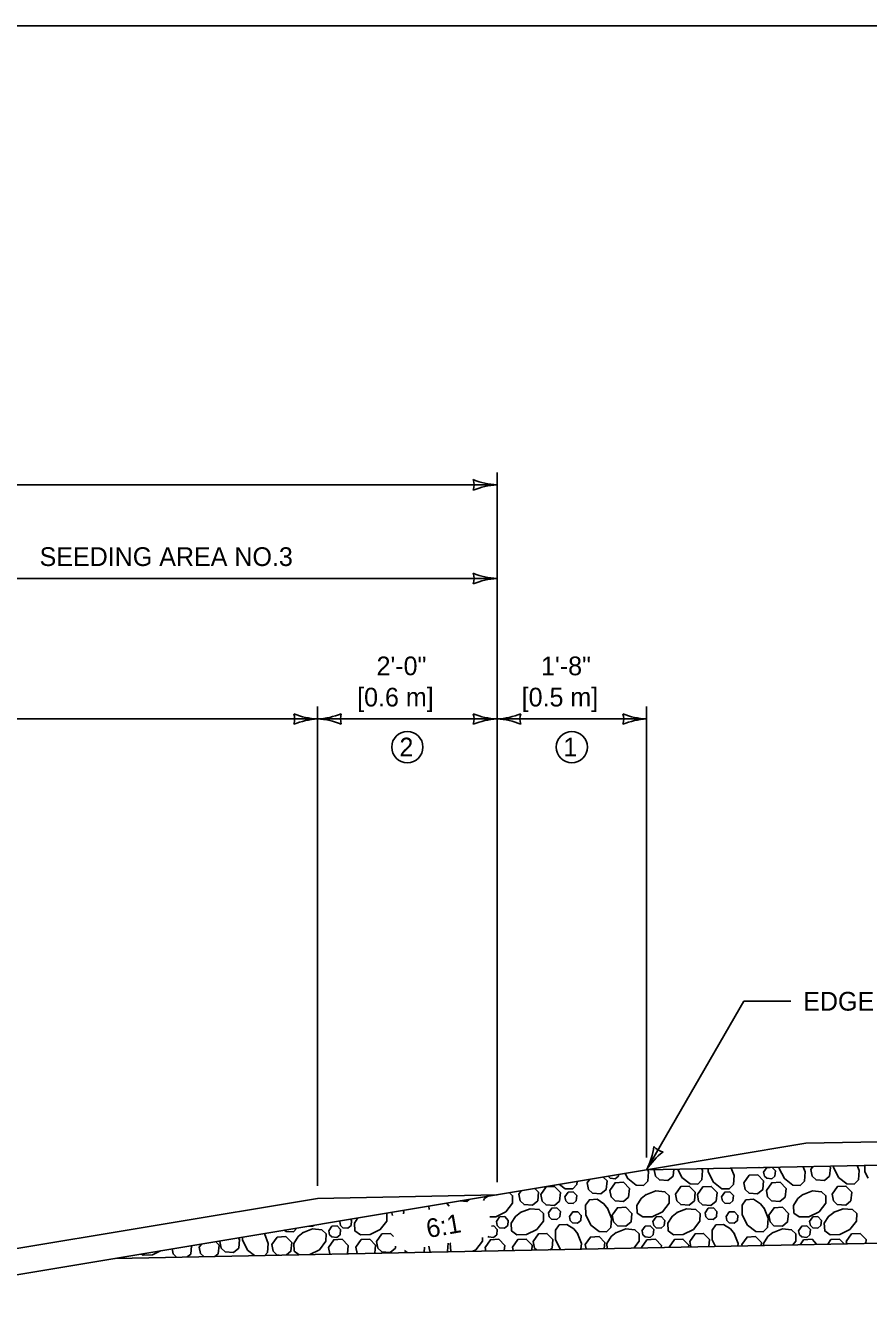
# Model space of a CAD drawing. Extents: x 49991.4 to 50021, y 49987.6 to 50011.4.
# Drawn here: x 50015.142 to 50017.842, y 50004.05 to 50008.165 of the extents above; entities that cross this region are included whole.
import ezdxf

# ---------------------------------------------------------------- set-up
doc = ezdxf.new("R2010")
doc.units = 0
for name, color, linetype in [('Level 1', 7, 'Continuous'), ('Level 2', 7, 'Continuous'), ('Level 3', 7, 'Continuous')]:
    doc.layers.add(name, color=color, linetype=linetype)

msp = doc.modelspace()

# ---------------------------------------------------------------- linework, layer by layer
at = {"layer": 'Level 1'}
for p, q in [((50020.1431, 50004.6348), (50017.6426, 50004.5848)), ((50017.6426, 50004.5848), (50017.132, 50004.4997)), ((50017.132, 50004.4997), (50020.1446, 50004.5599)), ((50014.9506, 50004.1361), (50017.132, 50004.4997)), ((50016.6527, 50004.4198), (50016.0776, 50004.4083)), ((50014.9506, 50004.2205), (50016.0776, 50004.4083)), ((50020.1496, 50004.3104), (50015.4298, 50004.216))]:
    msp.add_line(p, q, dxfattribs=at)
msp.add_lwpolyline([(50020.9378, 50008.1646), (50009.7374, 50008.1646), (50009.7374, 49999.8856), (50020.9378, 49999.8856)], close=True, dxfattribs=at)
for points in [[(50017.1357, 50004.4998), (50017.1384, 50004.4931), (50017.1358, 50004.4638), (50017.1226, 50004.4499), (50017.0988, 50004.4504), (50017.0718, 50004.4715), (50017.0634, 50004.4883)], [(50017.219, 50004.5014), (50017.2168, 50004.4796), (50017.2, 50004.4656), (50017.1731, 50004.4676), (50017.1605, 50004.4798), (50017.1565, 50004.5002)], [(50017.3093, 50004.5032), (50017.3116, 50004.4973), (50017.3091, 50004.468), (50017.2959, 50004.454), (50017.2721, 50004.4545), (50017.2451, 50004.4756), (50017.232, 50004.5017)], [(50017.4034, 50004.5051), (50017.4127, 50004.4818), (50017.4102, 50004.4525), (50017.3969, 50004.4386), (50017.3732, 50004.439), (50017.3461, 50004.4601), (50017.3298, 50004.4928), (50017.3296, 50004.5036)], [(50017.4922, 50004.5069), (50017.4922, 50004.5069), (50017.4918, 50004.5069)], [(50017.5339, 50004.5077), (50017.545, 50004.4962), (50017.5434, 50004.4797), (50017.5333, 50004.4713), (50017.5172, 50004.4725), (50017.5096, 50004.4798), (50017.5071, 50004.4925)], [(50017.5071, 50004.4925), (50017.5173, 50004.507), (50017.5277, 50004.5076)], [(50017.6336, 50004.5097), (50017.6401, 50004.4931), (50017.6376, 50004.4638), (50017.6244, 50004.4499), (50017.6006, 50004.4504), (50017.5736, 50004.4715), (50017.5573, 50004.5041), (50017.5572, 50004.5082)], [(50017.7172, 50004.5114), (50017.7213, 50004.5071), (50017.7186, 50004.4796), (50017.7018, 50004.4656), (50017.6749, 50004.4676), (50017.6622, 50004.4798), (50017.6581, 50004.5009)], [(50017.6581, 50004.5009), (50017.6648, 50004.5103)], [(50017.8071, 50004.5132), (50017.8134, 50004.4973), (50017.8109, 50004.468), (50017.7976, 50004.454), (50017.7739, 50004.4545), (50017.7469, 50004.4756), (50017.7305, 50004.5083), (50017.7305, 50004.5117)], [(50017.8416, 50004.4729), (50017.8316, 50004.4928), (50017.8312, 50004.5137)], [(50016.9093, 50004.4626), (50016.9084, 50004.4525), (50016.8952, 50004.4386), (50016.8714, 50004.439), (50016.8532, 50004.4532)], [(50016.9932, 50004.4766), (50017.0052, 50004.4641), (50017.0024, 50004.4366), (50016.9856, 50004.4226), (50016.9587, 50004.4246), (50016.9461, 50004.4369), (50016.942, 50004.4579)], [(50016.942, 50004.4579), (50016.95, 50004.4694)], [(50017.0421, 50004.4847), (50017.0416, 50004.4797), (50017.0315, 50004.4713), (50017.0154, 50004.4725), (50017.0085, 50004.4791)], [(50017.014, 50004.4339), (50017.0311, 50004.4581), (50017.0583, 50004.4597), (50017.0772, 50004.4401), (50017.0745, 50004.4125), (50017.0577, 50004.3986), (50017.0308, 50004.4005), (50017.0181, 50004.4128), (50017.014, 50004.4339)], [(50017.4438, 50004.4579), (50017.4608, 50004.4822), (50017.488, 50004.4837), (50017.5069, 50004.4641), (50017.5042, 50004.4366), (50017.4874, 50004.4226), (50017.4605, 50004.4246), (50017.4479, 50004.4369), (50017.4438, 50004.4579)], [(50017.5158, 50004.4339), (50017.5329, 50004.4581), (50017.5601, 50004.4597), (50017.579, 50004.4401), (50017.5763, 50004.4125), (50017.5594, 50004.3986), (50017.5326, 50004.4005), (50017.5199, 50004.4128), (50017.5158, 50004.4339)], [(50016.6091, 50004.4017), (50016.6129, 50004.4076), (50016.6217, 50004.4146)], [(50016.6924, 50004.4264), (50016.7028, 50004.4165), (50016.7024, 50004.3927), (50016.6812, 50004.3657), (50016.6486, 50004.3494), (50016.6295, 50004.349)], [(50016.7743, 50004.4401), (50016.786, 50004.428), (50016.7832, 50004.4005), (50016.7664, 50004.3866), (50016.7395, 50004.3885), (50016.7269, 50004.4008), (50016.7228, 50004.4218)], [(50016.7228, 50004.4218), (50016.7305, 50004.4328)], [(50016.7929, 50004.4208), (50016.81, 50004.4451), (50016.8372, 50004.4466), (50016.8561, 50004.427), (50016.8534, 50004.3995), (50016.8365, 50004.3855), (50016.8097, 50004.3875), (50016.797, 50004.3997), (50016.7929, 50004.4208)], [(50016.8705, 50004.4133), (50016.8807, 50004.4279), (50016.8971, 50004.4288), (50016.9084, 50004.417), (50016.9068, 50004.4005), (50016.8967, 50004.3921), (50016.8805, 50004.3933), (50016.873, 50004.4007), (50016.8705, 50004.4133)], [(50017.1295, 50004.4196), (50017.1614, 50004.4323), (50017.1907, 50004.4297), (50017.2046, 50004.4165), (50017.2041, 50004.3927), (50017.183, 50004.3657), (50017.1503, 50004.3494), (50017.1196, 50004.3488), (50017.1022, 50004.3611), (50017.1006, 50004.3857), (50017.1147, 50004.4076), (50017.1308, 50004.4204)], [(50017.2246, 50004.4218), (50017.2416, 50004.4461), (50017.2688, 50004.4476), (50017.2878, 50004.428), (50017.285, 50004.4005), (50017.2682, 50004.3866), (50017.2413, 50004.3885), (50017.2287, 50004.4008), (50017.2246, 50004.4218)], [(50017.2947, 50004.4208), (50017.3117, 50004.4451), (50017.339, 50004.4466), (50017.3579, 50004.427), (50017.3552, 50004.3995), (50017.3383, 50004.3855), (50017.3115, 50004.3875), (50017.2988, 50004.3997), (50017.2947, 50004.4208)], [(50017.3723, 50004.4133), (50017.3825, 50004.4279), (50017.3988, 50004.4288), (50017.4102, 50004.417), (50017.4085, 50004.4005), (50017.3985, 50004.3921), (50017.3823, 50004.3933), (50017.3747, 50004.4007), (50017.3723, 50004.4133)], [(50017.6313, 50004.4196), (50017.6631, 50004.4323), (50017.6925, 50004.4297), (50017.7064, 50004.4165), (50017.7059, 50004.3927), (50017.6848, 50004.3657), (50017.6521, 50004.3494), (50017.6214, 50004.3488), (50017.604, 50004.3611), (50017.6024, 50004.3857), (50017.6164, 50004.4076), (50017.6325, 50004.4204)], [(50017.7264, 50004.4218), (50017.7434, 50004.4461), (50017.7706, 50004.4476), (50017.7895, 50004.428), (50017.7868, 50004.4005), (50017.77, 50004.3866), (50017.7431, 50004.3885), (50017.7305, 50004.4008), (50017.7264, 50004.4218)], [(50016.3504, 50004.3694), (50016.3538, 50004.3659), (50016.3532, 50004.3593)], [(50016.4348, 50004.3728), (50016.4346, 50004.3835)], [(50016.4909, 50004.3928), (50016.4933, 50004.3913), (50016.4995, 50004.3835)], [(50016.5636, 50004.405), (50016.5559, 50004.3986), (50016.5345, 50004.4001)], [(50016.7266, 50004.3627), (50016.7585, 50004.3753), (50016.7878, 50004.3728), (50016.8018, 50004.3595), (50016.8013, 50004.3357), (50016.7802, 50004.3087), (50016.7475, 50004.2924), (50016.7167, 50004.2919), (50016.6994, 50004.3042), (50016.6978, 50004.3287), (50016.7118, 50004.3506), (50016.7279, 50004.3635)], [(50016.8177, 50004.3621), (50016.8279, 50004.3767), (50016.8443, 50004.3776), (50016.8556, 50004.3659), (50016.854, 50004.3494), (50016.8439, 50004.341), (50016.8278, 50004.3422), (50016.8202, 50004.3495), (50016.8177, 50004.3621)], [(50017.0071, 50004.3765), (50017.0198, 50004.3446), (50017.0172, 50004.3153), (50017.004, 50004.3014), (50016.9802, 50004.3018), (50016.9532, 50004.323), (50016.9369, 50004.3556), (50016.9363, 50004.3864), (50016.9486, 50004.4037), (50016.9732, 50004.4054), (50016.9951, 50004.3913), (50017.0079, 50004.3752)], [(50017.0216, 50004.3541), (50017.0386, 50004.3783), (50017.0659, 50004.3799), (50017.0848, 50004.3603), (50017.0821, 50004.3328), (50017.0652, 50004.3188), (50017.0384, 50004.3207), (50017.0257, 50004.333), (50017.0216, 50004.3541)], [(50017.2284, 50004.3627), (50017.2603, 50004.3753), (50017.2896, 50004.3728), (50017.3035, 50004.3595), (50017.3031, 50004.3357), (50017.282, 50004.3087), (50017.2493, 50004.2924), (50017.2185, 50004.2919), (50017.2012, 50004.3042), (50017.1996, 50004.3287), (50017.2136, 50004.3506), (50017.2297, 50004.3635)], [(50017.3195, 50004.3621), (50017.3297, 50004.3767), (50017.3461, 50004.3776), (50017.3574, 50004.3659), (50017.3558, 50004.3494), (50017.3457, 50004.341), (50017.3296, 50004.3422), (50017.322, 50004.3495), (50017.3195, 50004.3621)], [(50017.5089, 50004.3765), (50017.5215, 50004.3446), (50017.519, 50004.3153), (50017.5058, 50004.3014), (50017.482, 50004.3018), (50017.455, 50004.323), (50017.4387, 50004.3556), (50017.4381, 50004.3864), (50017.4504, 50004.4037), (50017.4749, 50004.4054), (50017.4969, 50004.3913), (50017.5097, 50004.3752)], [(50017.5234, 50004.3541), (50017.5404, 50004.3783), (50017.5677, 50004.3799), (50017.5866, 50004.3603), (50017.5838, 50004.3328), (50017.567, 50004.3188), (50017.5401, 50004.3207), (50017.5275, 50004.333), (50017.5234, 50004.3541)], [(50017.7302, 50004.3627), (50017.7621, 50004.3753), (50017.7914, 50004.3728), (50017.8053, 50004.3595), (50017.8049, 50004.3357), (50017.7837, 50004.3087), (50017.7511, 50004.2924), (50017.7203, 50004.2919), (50017.703, 50004.3042), (50017.7013, 50004.3287), (50017.7154, 50004.3506), (50017.7315, 50004.3635)], [(50016.1832, 50004.3416), (50016.1868, 50004.3379), (50016.1851, 50004.3214), (50016.175, 50004.313), (50016.1589, 50004.3142), (50016.1513, 50004.3215), (50016.1489, 50004.3342)], [(50016.1489, 50004.3342), (50016.1502, 50004.3361)], [(50016.2986, 50004.3608), (50016.3, 50004.3595), (50016.2995, 50004.3357), (50016.2784, 50004.3087), (50016.2457, 50004.2924), (50016.215, 50004.2919), (50016.1976, 50004.3042), (50016.196, 50004.3287), (50016.2067, 50004.3455)], [(50016.3159, 50004.3621), (50016.3172, 50004.3639)], [(50016.3176, 50004.3534), (50016.3159, 50004.3621)], [(50016.6506, 50004.3342), (50016.6609, 50004.3487), (50016.6772, 50004.3497), (50016.6885, 50004.3379), (50016.6869, 50004.3214), (50016.6768, 50004.313), (50016.6607, 50004.3142), (50016.6531, 50004.3215), (50016.6506, 50004.3342)], [(50016.8849, 50004.3502), (50016.8951, 50004.3647), (50016.9114, 50004.3656), (50016.9228, 50004.3539), (50016.9211, 50004.3374), (50016.9111, 50004.329), (50016.8949, 50004.3302), (50016.8873, 50004.3375), (50016.8849, 50004.3502)], [(50017.1524, 50004.3342), (50017.1627, 50004.3487), (50017.179, 50004.3497), (50017.1903, 50004.3379), (50017.1887, 50004.3214), (50017.1786, 50004.313), (50017.1625, 50004.3142), (50017.1549, 50004.3215), (50017.1524, 50004.3342)], [(50017.3867, 50004.3502), (50017.3969, 50004.3647), (50017.4132, 50004.3656), (50017.4246, 50004.3539), (50017.4229, 50004.3374), (50017.4129, 50004.329), (50017.3967, 50004.3302), (50017.3891, 50004.3375), (50017.3867, 50004.3502)], [(50017.6542, 50004.3342), (50017.6644, 50004.3487), (50017.6808, 50004.3497), (50017.6921, 50004.3379), (50017.6905, 50004.3214), (50017.6804, 50004.313), (50017.6643, 50004.3142), (50017.6567, 50004.3215), (50017.6542, 50004.3342)], [(50015.9073, 50004.2956), (50015.9197, 50004.2642), (50015.9172, 50004.2349), (50015.9083, 50004.2256)], [(50015.9073, 50004.2956), (50015.9079, 50004.2948)], [(50015.9316, 50004.2603), (50015.9487, 50004.2845), (50015.9759, 50004.2861), (50015.9948, 50004.2665), (50015.9921, 50004.239), (50015.9776, 50004.227)], [(50016.0114, 50004.3129), (50016.0004, 50004.3014), (50015.9766, 50004.3018), (50015.9711, 50004.3062)], [(50016.0188, 50004.2278), (50016.0027, 50004.2392), (50016.0011, 50004.2637), (50016.0151, 50004.2857), (50016.0312, 50004.2985)], [(50016.0299, 50004.2977), (50016.0618, 50004.3103), (50016.0911, 50004.3078), (50016.1051, 50004.2946), (50016.1046, 50004.2708), (50016.0835, 50004.2438), (50016.0529, 50004.2285)], [(50016.0655, 50004.3219), (50016.0617, 50004.3188), (50016.0511, 50004.3195)], [(50016.1137, 50004.3046), (50016.1239, 50004.3192), (50016.1402, 50004.3201), (50016.1516, 50004.3083), (50016.15, 50004.2918), (50016.1399, 50004.2834), (50016.1237, 50004.2846), (50016.1162, 50004.2919), (50016.1137, 50004.3046)], [(50016.2666, 50004.2701), (50016.2837, 50004.2943), (50016.3109, 50004.2959), (50016.3206, 50004.2858)], [(50016.6348, 50004.3197), (50016.642, 50004.3201), (50016.6534, 50004.3083), (50016.6517, 50004.2918), (50016.6416, 50004.2834), (50016.6255, 50004.2846), (50016.6237, 50004.2863)], [(50016.7684, 50004.2701), (50016.7854, 50004.2943), (50016.8127, 50004.2959), (50016.8316, 50004.2763), (50016.8289, 50004.2488), (50016.8229, 50004.2439)], [(50016.8557, 50004.2445), (50016.8404, 50004.2752), (50016.8399, 50004.306), (50016.8522, 50004.3233), (50016.8767, 50004.3249), (50016.8986, 50004.3109), (50016.9115, 50004.2948)], [(50016.9106, 50004.2961), (50016.9233, 50004.2642), (50016.9217, 50004.2458)], [(50016.9352, 50004.2603), (50016.9522, 50004.2845), (50016.9795, 50004.2861), (50016.9984, 50004.2665), (50016.9965, 50004.2473)], [(50017.0057, 50004.2475), (50017.0046, 50004.2637), (50017.0187, 50004.2857), (50017.0348, 50004.2985)], [(50017.0335, 50004.2977), (50017.0654, 50004.3103), (50017.0947, 50004.3078), (50017.1086, 50004.2946), (50017.1082, 50004.2708), (50017.0913, 50004.2492)], [(50017.1172, 50004.3046), (50017.1275, 50004.3192), (50017.1438, 50004.3201), (50017.1552, 50004.3083), (50017.1535, 50004.2918), (50017.1434, 50004.2834), (50017.1273, 50004.2846), (50017.1197, 50004.2919), (50017.1173, 50004.3046)], [(50017.2702, 50004.2701), (50017.2872, 50004.2943), (50017.3145, 50004.2959), (50017.3334, 50004.2763), (50017.3312, 50004.254)], [(50017.3525, 50004.2545), (50017.3422, 50004.2752), (50017.3416, 50004.306), (50017.354, 50004.3233), (50017.3785, 50004.3249), (50017.4004, 50004.3109), (50017.4132, 50004.2948)], [(50017.4124, 50004.2961), (50017.4251, 50004.2642), (50017.4244, 50004.2559)], [(50017.437, 50004.2603), (50017.454, 50004.2845), (50017.4813, 50004.2861), (50017.5002, 50004.2665), (50017.4993, 50004.2574)], [(50017.5068, 50004.2575), (50017.5064, 50004.2637), (50017.5205, 50004.2857), (50017.5366, 50004.2985)], [(50017.5353, 50004.2977), (50017.5672, 50004.3103), (50017.5965, 50004.3078), (50017.6104, 50004.2946), (50017.61, 50004.2708), (50017.6011, 50004.2594)], [(50017.619, 50004.3046), (50017.6293, 50004.3192), (50017.6456, 50004.3201), (50017.6569, 50004.3083), (50017.6553, 50004.2918), (50017.6452, 50004.2834), (50017.6291, 50004.2846), (50017.6215, 50004.2919), (50017.619, 50004.3046)], [(50017.772, 50004.2701), (50017.789, 50004.2943), (50017.8162, 50004.2959), (50017.8352, 50004.2763), (50017.834, 50004.2641)], [(50015.6255, 50004.2199), (50015.6149, 50004.2302), (50015.6117, 50004.2463)], [(50015.6739, 50004.2567), (50015.6712, 50004.23), (50015.6599, 50004.2206)], [(50015.6987, 50004.2523), (50015.7055, 50004.2619)], [(50015.7127, 50004.2217), (50015.7028, 50004.2312), (50015.6987, 50004.2523)], [(50015.7512, 50004.2696), (50015.7619, 50004.2585), (50015.7592, 50004.231), (50015.7488, 50004.2224)], [(50015.823, 50004.2815), (50015.828, 50004.2763), (50015.8253, 50004.2488), (50015.8085, 50004.2348), (50015.7816, 50004.2367), (50015.769, 50004.249), (50015.7648, 50004.2701)], [(50015.7648, 50004.2701), (50015.7662, 50004.2721)], [(50015.8757, 50004.2249), (50015.8531, 50004.2425), (50015.8368, 50004.2752), (50015.8367, 50004.2838)], [(50015.9546, 50004.2265), (50015.9484, 50004.2269), (50015.9357, 50004.2392), (50015.9316, 50004.2603)], [(50016.1125, 50004.2513), (50016.1296, 50004.2755), (50016.1568, 50004.2771), (50016.1757, 50004.2575), (50016.1731, 50004.2309)], [(50016.1171, 50004.2297), (50016.1167, 50004.2302), (50016.1126, 50004.2513)], [(50016.2005, 50004.2523), (50016.2175, 50004.2765), (50016.2448, 50004.2781), (50016.2637, 50004.2585), (50016.2611, 50004.2326)], [(50016.2046, 50004.2315), (50016.2005, 50004.2523)], [(50016.3277, 50004.2549), (50016.3271, 50004.2488), (50016.3103, 50004.2348), (50016.2834, 50004.2367), (50016.2707, 50004.249), (50016.2666, 50004.2701)], [(50016.4205, 50004.2524), (50016.419, 50004.2358)], [(50016.4406, 50004.2362), (50016.4375, 50004.2392), (50016.4345, 50004.2548)], [(50016.4965, 50004.2651), (50016.4939, 50004.239), (50016.4918, 50004.2372)], [(50016.5068, 50004.2375), (50016.5045, 50004.2392), (50016.5029, 50004.2637), (50016.5046, 50004.2664)], [(50016.6066, 50004.2834), (50016.6064, 50004.2708), (50016.5853, 50004.2438), (50016.5756, 50004.2389)], [(50016.6143, 50004.2513), (50016.6314, 50004.2755), (50016.6586, 50004.2771), (50016.6775, 50004.2575), (50016.6759, 50004.2409)], [(50016.6166, 50004.2397), (50016.6143, 50004.2513)], [(50016.7023, 50004.2523), (50016.7193, 50004.2765), (50016.7466, 50004.2781), (50016.7655, 50004.2585), (50016.7639, 50004.2427)], [(50016.7044, 50004.2415), (50016.7023, 50004.2523)], [(50016.7787, 50004.243), (50016.7725, 50004.249), (50016.7684, 50004.2701)], [(50016.938, 50004.2462), (50016.9352, 50004.2603)], [(50017.1161, 50004.2513), (50017.1332, 50004.2755), (50017.1604, 50004.2771), (50017.1793, 50004.2575), (50017.1787, 50004.251)], [(50017.1164, 50004.2497), (50017.1161, 50004.2513)], [(50017.2041, 50004.2523), (50017.2211, 50004.2765), (50017.2483, 50004.2781), (50017.2673, 50004.2585), (50017.2667, 50004.2527)], [(50017.2042, 50004.2515), (50017.2041, 50004.2523)], [(50017.2736, 50004.2529), (50017.2702, 50004.2701)], [(50017.4378, 50004.2562), (50017.437, 50004.2603)], [(50017.6239, 50004.2599), (50017.6349, 50004.2755), (50017.6622, 50004.2771), (50017.6777, 50004.261)], [(50017.7124, 50004.2617), (50017.7229, 50004.2765), (50017.7501, 50004.2781), (50017.765, 50004.2627)], [(50017.7734, 50004.2629), (50017.772, 50004.2701)], [(50015.5743, 50004.2401), (50015.549, 50004.2274), (50015.5183, 50004.2269), (50015.5139, 50004.23)], [(50016.3649, 50004.2347), (50016.356, 50004.2417)]]:
    msp.add_lwpolyline(points, dxfattribs=at)
at = {"layer": 'Level 2'}
for centre in [(50016.3652, 50005.8539), (50016.8924, 50005.8539)]:
    msp.add_circle(centre, 0.05, dxfattribs=at)
at = {"layer": 'Level 3'}
for p, q in [((50016.6527, 50004.4598), (50016.6527, 50006.7339)), ((50010.5256, 50006.6939), (50016.6527, 50006.6939)), ((50014.6255, 50006.3939), (50016.6527, 50006.3939)), ((50016.0776, 50004.4483), (50016.0776, 50005.9839)), ((50017.132, 50005.9439), (50017.132, 50005.9839)), ((50012.2773, 50005.9439), (50016.0776, 50005.9439)), ((50016.0776, 50005.9439), (50016.6527, 50005.9439)), ((50017.132, 50005.9439), (50016.6527, 50005.9439)), ((50017.132, 50004.5397), (50017.132, 50005.9439)), ((50017.132, 50004.4997), (50017.4438, 50005.0397)), ((50017.4438, 50005.0397), (50017.5938, 50005.0397))]:
    msp.add_line(p, q, dxfattribs=at)
for centre, radius, start, end in [((50016.6619, 50006.916), 0.2223, 247.456, 267.6395), ((50016.5245, 50006.6939), 0.0548, 342.1388, 17.8612), ((50016.6642, 50006.4611), 0.233, 92.8273, 112.0772), ((50016.6619, 50006.616), 0.2223, 247.456, 267.6395), ((50016.5245, 50006.3939), 0.0548, 342.1388, 17.8612), ((50016.6642, 50006.1611), 0.233, 92.8273, 112.0772), ((50016.0868, 50006.166), 0.2223, 247.456, 267.6395), ((50015.9494, 50005.9439), 0.0548, 342.1388, 17.8612), ((50016.0891, 50005.7111), 0.233, 92.8273, 112.0772), ((50016.0662, 50006.1766), 0.233, 272.8273, 292.0772), ((50016.0685, 50005.7217), 0.2223, 67.456, 87.6395), ((50016.2059, 50005.9439), 0.0548, 162.1388, 197.8612), ((50016.6619, 50006.166), 0.2223, 247.456, 267.6395), ((50016.5245, 50005.9439), 0.0548, 342.1388, 17.8612), ((50016.6642, 50005.7111), 0.233, 92.8273, 112.0772), ((50016.6413, 50006.1766), 0.233, 272.8273, 292.0772), ((50016.6436, 50005.7217), 0.2223, 67.456, 87.6395), ((50016.781, 50005.9439), 0.0548, 162.1388, 197.8612), ((50017.1412, 50006.166), 0.2223, 247.456, 267.6395), ((50017.0038, 50005.9439), 0.0548, 342.1388, 17.8612), ((50017.1435, 50005.7111), 0.233, 92.8273, 112.0772), ((50016.9247, 50004.6061), 0.233, 332.8273, 352.0772), ((50016.9247, 50004.6061), 0.233, 332.8273, 352.0772), ((50017.1961, 50004.6107), 0.0548, 222.1388, 257.8612), ((50017.1961, 50004.6107), 0.0548, 222.1388, 257.8612), ((50017.3198, 50004.3807), 0.2223, 127.456, 147.6395), ((50017.3198, 50004.3807), 0.2223, 127.456, 147.6395)]:
    msp.add_arc(centre, radius, start, end, dxfattribs=at)

# ---------------------------------------------------------------- texts
at = {"layer": 'Level 2'}
for s, p in [('SEEDING AREA NO.3', (50015.1869, 50006.4339)), ('2\'-0"', (50016.2667, 50006.0839)), ('1\'-8"', (50016.7939, 50006.0839)), ('[0.6 m]', (50016.2045, 50005.9839)), ('[0.5 m]', (50016.7317, 50005.9839)), ('2', (50016.34, 50005.8239)), ('1', (50016.865, 50005.8239)), ('EDGE OF PAVEMENT', (50017.6338, 50005.0097))]:
    msp.add_text(s, height=0.06, dxfattribs=at).set_placement(p)
msp.add_text('6:1', height=0.06, rotation=10, dxfattribs=at).set_placement((50016.4315, 50004.2811))

doc.saveas('drawing.dxf')
